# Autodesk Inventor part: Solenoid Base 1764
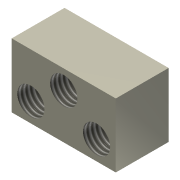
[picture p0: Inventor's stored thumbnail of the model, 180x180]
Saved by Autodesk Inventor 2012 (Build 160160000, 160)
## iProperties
Created: 2010-02
Part Number: Solenoid Base 1764
Document SubType Name: Modeling
Designer: jgehrig
Density: 1 g/cm^3
Material: Default
Author: jgehrig
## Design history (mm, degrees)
sketch "Sketch1"
  geometry: L1 (-30.233, 17.868)-(11.042, 17.868); L2 (11.042, 17.868)-(11.042, -7.532); L3 (11.042, -7.532)-(-30.233, -7.532); L4 (-30.233, -7.532)-(-30.233, 17.868); 1 further point
  constraints: 8 end point, 2 parallel, 1 horizontal, 1 perpendicular
  dimensions: "d0" = 41.275 distance of L1.start L1.end; "d1" = 25.4 distance of L3.end L1.start
extrude "Extrusion1" new body sketch "Sketch1" distance "d2" = 20.955; taper "d3" = 0 deg
sketch "Sketch2"
  geometry: L1 (11.042, 17.868)-(11.042, -7.532) reference; L2 (-30.233, 17.868)-(11.042, 17.868) reference; L3 (-30.233, -7.532)-(-30.233, 17.868) reference; L4 (11.042, -7.532)-(-30.233, -7.532) reference; C1 r 5.397 at (-9.595, 10.248); C2 r 5.397 at (-22.613, 0.088); C3 r 5.397 at (3.422, 0.088)
  constraints: 3 centre point, 2 equal radius
  dimensions: "d4" = 10.795 diameter of C1; "d5" = 7.62 distance from line of L2 C1.centre; "d6" = 7.62 distance from line of L4 C2.centre; "d7" = 7.62 distance from line of L4 C3.centre; "d8" = 7.62 distance from line of L3 C2.centre; "d9" = 7.62 distance from line of L1 C3.centre
extrude "Extrusion2" cut sketch "Sketch2" distance "d10" = 9.525; taper "d11" = 0 deg
thread "Thread1" dims "d12" = 25.4, "d13" = 0
thread "Thread2" dims "d14" = 25.4, "d15" = 0
thread "Thread3" dims "d16" = 25.4, "d17" = 0
sketch "Sketch3"
  geometry: L1 (30.233, -7.532)-(30.233, 17.868) reference; C1 r 5.397 at (0.07, 5.168); C2 r 5.397 at (19.12, 5.168); 1 further point
  constraints: 2 centre point, 1 equal radius
  dimensions: "d18" = 10.795 diameter of C1; "d19" = 19.05 distance of C2.centre C1.centre; "d20" = 11.1125 distance from line of L1 C2.centre
extrude "Extrusion3" cut sketch "Sketch3" distance "d21" = 9.525; taper "d22" = 0 deg
thread "Thread4" dims "d23" = 25.4, "d24" = 0
thread "Thread5" dims "d25" = 25.4, "d26" = 0
body "Solid1"
